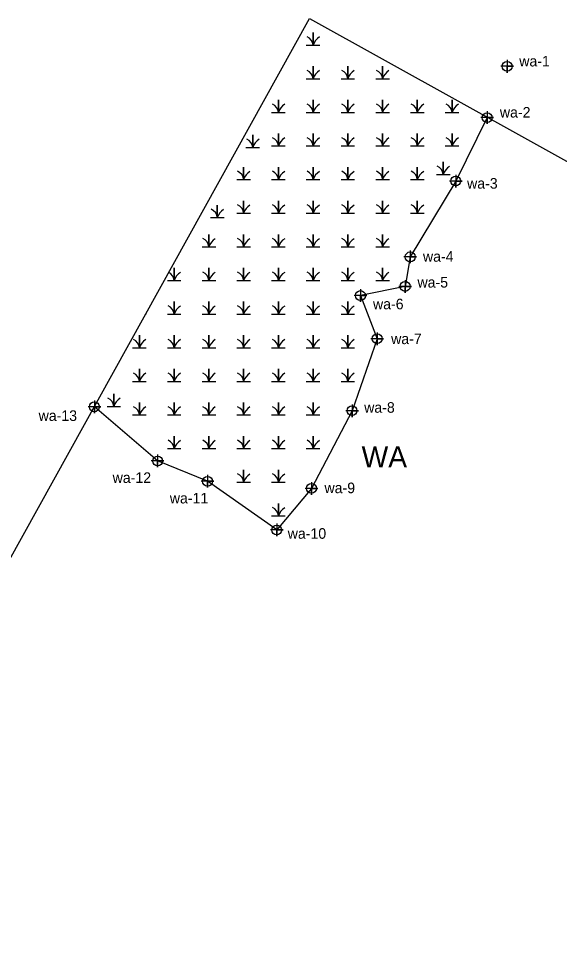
# Model space of a CAD drawing. Extents: x 2174810 to 2196950, y 76168 to 88270.
# Drawn here: x 2177275 to 2177531.1, y 78724.8 to 79164 of the extents above; entities that cross this region are included whole.
import ezdxf

# ---------------------------------------------------------------- set-up
doc = ezdxf.new("R2010")
doc.units = 0
for name, color, linetype in [('Default', 7, 'Continuous'), ('Exist Environmental Wetland Boundary', 7, 'Continuous'), ('Exist Environmental Wetland Boundary Cogo Number', 7, 'Continuous'), ('Exist Environmental Wetland Boundary Cogo Point CELL', 7, 'Continuous'), ('Exist Environmental Wetland Boundary Text', 7, 'Continuous'), ('Exist Hydro Swamp or Marsh', 7, 'Continuous')]:
    doc.layers.add(name, color=color, linetype=linetype)

msp = doc.modelspace()

# ---------------------------------------------------------------- linework, layer by layer
at = {"layer": 'Default'}
msp.add_lwpolyline([(2175864.96, 77468.65), (2175974.98, 78067.37), (2175948.66, 78270.55), (2176147, 78296.25), (2176199.64, 77889.88), (2176204.55, 77860.59), (2176211.62, 77831.74), (2176220.8, 77803.5), (2176232.06, 77776.01), (2176245.32, 77749.44), (2176260.52, 77723.93), (2176492.8, 77599.18), (2176546.77, 77667.81), (2176598.73, 77737.98), (2176648.61, 77809.64), (2176696.4, 77882.71), (2176742.03, 77957.15), (2176785.48, 78032.88), (2177412.72, 79163.99), (2177762.53, 78970.01), (2177135.29, 77838.9), (2177091.17, 77761.72), (2177045.03, 77685.72), (2176996.93, 77610.95)], dxfattribs=at)
at = {"layer": 'Exist Environmental Wetland Boundary'}
msp.add_lwpolyline([(2177496.94, 79117.29), (2177496.87, 79117.09), (2177481.99, 79087.09), (2177460.42, 79051.18), (2177458.02, 79037.2), (2177436.88, 79032.86), (2177444.78, 79012.46), (2177432.88, 78978.36), (2177413.67, 78941.61), (2177397.22, 78921.92), (2177364.45, 78944.95), (2177340.81, 78954.58), (2177310.88, 78980.2)], dxfattribs=at)
at = {"layer": 'Exist Environmental Wetland Boundary Cogo Point CELL'}
for points in [[(2177506.32, 79144.38), (2177506.32, 79138.38), (2177506.32, 79141.38), (2177509.32, 79141.38), (2177503.32, 79141.38)], [(2177496.87, 79120.09), (2177496.87, 79114.09), (2177496.87, 79117.09), (2177499.87, 79117.09), (2177493.87, 79117.09)], [(2177481.99, 79090.09), (2177481.99, 79084.09), (2177481.99, 79087.09), (2177484.99, 79087.09), (2177478.99, 79087.09)], [(2177460.42, 79054.18), (2177460.42, 79048.18), (2177460.42, 79051.18), (2177463.42, 79051.18), (2177457.42, 79051.18)], [(2177458.02, 79040.2), (2177458.02, 79034.2), (2177458.02, 79037.2), (2177461.02, 79037.2), (2177455.02, 79037.2)], [(2177436.88, 79035.86), (2177436.88, 79029.86), (2177436.88, 79032.86), (2177439.88, 79032.86), (2177433.88, 79032.86)], [(2177444.78, 79015.46), (2177444.78, 79009.46), (2177444.78, 79012.46), (2177447.78, 79012.46), (2177441.78, 79012.46)], [(2177310.88, 78983.2), (2177310.88, 78977.2), (2177310.88, 78980.2), (2177313.88, 78980.2), (2177307.88, 78980.2)], [(2177432.88, 78981.36), (2177432.88, 78975.36), (2177432.88, 78978.36), (2177435.88, 78978.36), (2177429.88, 78978.36)], [(2177340.81, 78957.58), (2177340.81, 78951.58), (2177340.81, 78954.58), (2177343.81, 78954.58), (2177337.81, 78954.58)], [(2177364.45, 78947.95), (2177364.45, 78941.95), (2177364.45, 78944.95), (2177367.45, 78944.95), (2177361.45, 78944.95)], [(2177413.67, 78944.61), (2177413.67, 78938.61), (2177413.67, 78941.61), (2177416.67, 78941.61), (2177410.67, 78941.61)], [(2177397.22, 78924.92), (2177397.22, 78918.92), (2177397.22, 78921.92), (2177400.22, 78921.92), (2177394.22, 78921.92)]]:
    msp.add_lwpolyline(points, dxfattribs=at)
for centre in [(2177506.32, 79141.38), (2177496.87, 79117.09), (2177481.99, 79087.09), (2177460.42, 79051.18), (2177458.02, 79037.2), (2177436.88, 79032.86), (2177444.78, 79012.46), (2177310.88, 78980.2), (2177432.88, 78978.36), (2177340.81, 78954.58), (2177364.45, 78944.95), (2177413.67, 78941.61), (2177397.22, 78921.92)]:
    msp.add_circle(centre, 2.34, dxfattribs=at)
at = {"layer": 'Exist Hydro Swamp or Marsh'}
msp.add_line((2177335.2, 79024.09), (2177335.42, 79024.09), dxfattribs=at)
for points in [[(2177411.22, 79151.44), (2177414.45, 79151.44), (2177414.45, 79157.35), (2177414.45, 79151.44), (2177417.67, 79151.44)], [(2177411.22, 79135.52), (2177414.45, 79135.52), (2177414.45, 79141.44), (2177414.45, 79135.52), (2177417.67, 79135.52)], [(2177427.67, 79135.52), (2177430.9, 79135.52), (2177430.9, 79141.44), (2177430.9, 79135.52), (2177434.12, 79135.52)], [(2177444.12, 79135.52), (2177447.35, 79135.52), (2177447.35, 79141.44), (2177447.35, 79135.52), (2177450.57, 79135.52)], [(2177394.77, 79119.6), (2177398, 79119.6), (2177398, 79125.52), (2177398, 79119.6), (2177401.22, 79119.6)], [(2177411.22, 79119.6), (2177414.45, 79119.6), (2177414.45, 79125.52), (2177414.45, 79119.6), (2177417.67, 79119.6)], [(2177427.67, 79119.6), (2177430.9, 79119.6), (2177430.9, 79125.52), (2177430.9, 79119.6), (2177434.12, 79119.6)], [(2177444.12, 79119.6), (2177447.35, 79119.6), (2177447.35, 79125.52), (2177447.35, 79119.6), (2177450.57, 79119.6)], [(2177460.57, 79119.6), (2177463.8, 79119.6), (2177463.8, 79125.52), (2177463.8, 79119.6), (2177467.03, 79119.6)], [(2177477.03, 79119.6), (2177480.25, 79119.6), (2177480.25, 79125.52), (2177480.25, 79119.6), (2177483.48, 79119.6)], [(2177382.65, 79103.02), (2177385.87, 79103.02), (2177385.87, 79108.94), (2177385.87, 79103.02), (2177389.1, 79103.02)], [(2177394.77, 79103.68), (2177398, 79103.68), (2177398, 79109.6), (2177398, 79103.68), (2177401.22, 79103.68)], [(2177411.22, 79103.68), (2177414.45, 79103.68), (2177414.45, 79109.6), (2177414.45, 79103.68), (2177417.67, 79103.68)], [(2177427.67, 79103.68), (2177430.9, 79103.68), (2177430.9, 79109.6), (2177430.9, 79103.68), (2177434.12, 79103.68)], [(2177444.12, 79103.68), (2177447.35, 79103.68), (2177447.35, 79109.6), (2177447.35, 79103.68), (2177450.57, 79103.68)], [(2177460.57, 79103.68), (2177463.8, 79103.68), (2177463.8, 79109.6), (2177463.8, 79103.68), (2177467.03, 79103.68)], [(2177477.03, 79103.68), (2177480.25, 79103.68), (2177480.25, 79109.6), (2177480.25, 79103.68), (2177483.48, 79103.68)], [(2177378.32, 79087.76), (2177381.54, 79087.76), (2177381.54, 79093.68), (2177381.54, 79087.76), (2177384.77, 79087.76)], [(2177394.77, 79087.76), (2177398, 79087.76), (2177398, 79093.68), (2177398, 79087.76), (2177401.22, 79087.76)], [(2177411.22, 79087.76), (2177414.45, 79087.76), (2177414.45, 79093.68), (2177414.45, 79087.76), (2177417.67, 79087.76)], [(2177427.67, 79087.76), (2177430.9, 79087.76), (2177430.9, 79093.68), (2177430.9, 79087.76), (2177434.12, 79087.76)], [(2177444.12, 79087.76), (2177447.35, 79087.76), (2177447.35, 79093.68), (2177447.35, 79087.76), (2177450.57, 79087.76)], [(2177460.57, 79087.76), (2177463.8, 79087.76), (2177463.8, 79093.68), (2177463.8, 79087.76), (2177467.03, 79087.76)], [(2177472.84, 79090.2), (2177476.07, 79090.2), (2177476.07, 79096.12), (2177476.07, 79090.2), (2177479.3, 79090.2)], [(2177365.85, 79069.77), (2177369.08, 79069.77), (2177369.08, 79075.69), (2177369.08, 79069.77), (2177372.3, 79069.77)], [(2177378.32, 79071.85), (2177381.54, 79071.85), (2177381.54, 79077.76), (2177381.54, 79071.85), (2177384.77, 79071.85)], [(2177394.77, 79071.85), (2177398, 79071.85), (2177398, 79077.76), (2177398, 79071.85), (2177401.22, 79071.85)], [(2177411.22, 79071.85), (2177414.45, 79071.85), (2177414.45, 79077.76), (2177414.45, 79071.85), (2177417.67, 79071.85)], [(2177427.67, 79071.85), (2177430.9, 79071.85), (2177430.9, 79077.76), (2177430.9, 79071.85), (2177434.12, 79071.85)], [(2177444.12, 79071.85), (2177447.35, 79071.85), (2177447.35, 79077.76), (2177447.35, 79071.85), (2177450.57, 79071.85)], [(2177460.57, 79071.85), (2177463.8, 79071.85), (2177463.8, 79077.76), (2177463.8, 79071.85), (2177467.03, 79071.85)], [(2177361.87, 79055.93), (2177365.09, 79055.93), (2177365.09, 79061.85), (2177365.09, 79055.93), (2177368.32, 79055.93)], [(2177378.32, 79055.93), (2177381.54, 79055.93), (2177381.54, 79061.85), (2177381.54, 79055.93), (2177384.77, 79055.93)], [(2177394.77, 79055.93), (2177398, 79055.93), (2177398, 79061.85), (2177398, 79055.93), (2177401.22, 79055.93)], [(2177411.22, 79055.93), (2177414.45, 79055.93), (2177414.45, 79061.85), (2177414.45, 79055.93), (2177417.67, 79055.93)], [(2177427.67, 79055.93), (2177430.9, 79055.93), (2177430.9, 79061.85), (2177430.9, 79055.93), (2177434.12, 79055.93)], [(2177444.12, 79055.93), (2177447.35, 79055.93), (2177447.35, 79061.85), (2177447.35, 79055.93), (2177450.57, 79055.93)], [(2177345.42, 79040.01), (2177348.64, 79040.01), (2177348.64, 79045.93), (2177348.64, 79040.01), (2177351.87, 79040.01)], [(2177361.87, 79040.01), (2177365.09, 79040.01), (2177365.09, 79045.93), (2177365.09, 79040.01), (2177368.32, 79040.01)], [(2177378.32, 79040.01), (2177381.54, 79040.01), (2177381.54, 79045.93), (2177381.54, 79040.01), (2177384.77, 79040.01)], [(2177394.77, 79040.01), (2177398, 79040.01), (2177398, 79045.93), (2177398, 79040.01), (2177401.22, 79040.01)], [(2177411.22, 79040.01), (2177414.45, 79040.01), (2177414.45, 79045.93), (2177414.45, 79040.01), (2177417.67, 79040.01)], [(2177427.67, 79040.01), (2177430.9, 79040.01), (2177430.9, 79045.93), (2177430.9, 79040.01), (2177434.12, 79040.01)], [(2177444.12, 79040.01), (2177447.35, 79040.01), (2177447.35, 79045.93), (2177447.35, 79040.01), (2177450.57, 79040.01)], [(2177345.42, 79024.09), (2177348.64, 79024.09), (2177348.64, 79030.01), (2177348.64, 79024.09), (2177351.87, 79024.09)], [(2177361.87, 79024.09), (2177365.09, 79024.09), (2177365.09, 79030.01), (2177365.09, 79024.09), (2177368.32, 79024.09)], [(2177378.32, 79024.09), (2177381.54, 79024.09), (2177381.54, 79030.01), (2177381.54, 79024.09), (2177384.77, 79024.09)], [(2177394.77, 79024.09), (2177398, 79024.09), (2177398, 79030.01), (2177398, 79024.09), (2177401.22, 79024.09)], [(2177411.22, 79024.09), (2177414.45, 79024.09), (2177414.45, 79030.01), (2177414.45, 79024.09), (2177417.67, 79024.09)], [(2177427.67, 79024.09), (2177430.9, 79024.09), (2177430.9, 79030.01), (2177430.9, 79024.09), (2177434.12, 79024.09)], [(2177328.96, 79008.18), (2177332.19, 79008.18), (2177332.19, 79014.09), (2177332.19, 79008.18), (2177335.42, 79008.18)], [(2177345.42, 79008.18), (2177348.64, 79008.18), (2177348.64, 79014.09), (2177348.64, 79008.18), (2177351.87, 79008.18)], [(2177361.87, 79008.18), (2177365.09, 79008.18), (2177365.09, 79014.09), (2177365.09, 79008.18), (2177368.32, 79008.18)], [(2177378.32, 79008.18), (2177381.54, 79008.18), (2177381.54, 79014.09), (2177381.54, 79008.18), (2177384.77, 79008.18)], [(2177394.77, 79008.18), (2177398, 79008.18), (2177398, 79014.09), (2177398, 79008.18), (2177401.22, 79008.18)], [(2177411.22, 79008.18), (2177414.45, 79008.18), (2177414.45, 79014.09), (2177414.45, 79008.18), (2177417.67, 79008.18)], [(2177427.67, 79008.18), (2177430.9, 79008.18), (2177430.9, 79014.09), (2177430.9, 79008.18), (2177434.12, 79008.18)], [(2177328.96, 78992.26), (2177332.19, 78992.26), (2177332.19, 78998.18), (2177332.19, 78992.26), (2177335.42, 78992.26)], [(2177345.42, 78992.26), (2177348.64, 78992.26), (2177348.64, 78998.18), (2177348.64, 78992.26), (2177351.87, 78992.26)], [(2177361.87, 78992.26), (2177365.09, 78992.26), (2177365.09, 78998.18), (2177365.09, 78992.26), (2177368.32, 78992.26)], [(2177378.32, 78992.26), (2177381.54, 78992.26), (2177381.54, 78998.18), (2177381.54, 78992.26), (2177384.77, 78992.26)], [(2177394.77, 78992.26), (2177398, 78992.26), (2177398, 78998.18), (2177398, 78992.26), (2177401.22, 78992.26)], [(2177411.22, 78992.26), (2177414.45, 78992.26), (2177414.45, 78998.18), (2177414.45, 78992.26), (2177417.67, 78992.26)], [(2177427.67, 78992.26), (2177430.9, 78992.26), (2177430.9, 78998.18), (2177430.9, 78992.26), (2177434.12, 78992.26)], [(2177316.86, 78980.41), (2177320.08, 78980.41), (2177320.08, 78986.32), (2177320.08, 78980.41), (2177323.31, 78980.41)], [(2177328.96, 78976.34), (2177332.19, 78976.34), (2177332.19, 78982.26), (2177332.19, 78976.34), (2177335.42, 78976.34)], [(2177345.42, 78976.34), (2177348.64, 78976.34), (2177348.64, 78982.26), (2177348.64, 78976.34), (2177351.87, 78976.34)], [(2177361.87, 78976.34), (2177365.09, 78976.34), (2177365.09, 78982.26), (2177365.09, 78976.34), (2177368.32, 78976.34)], [(2177378.32, 78976.34), (2177381.54, 78976.34), (2177381.54, 78982.26), (2177381.54, 78976.34), (2177384.77, 78976.34)], [(2177394.77, 78976.34), (2177398, 78976.34), (2177398, 78982.26), (2177398, 78976.34), (2177401.22, 78976.34)], [(2177411.22, 78976.34), (2177414.45, 78976.34), (2177414.45, 78982.26), (2177414.45, 78976.34), (2177417.67, 78976.34)], [(2177345.42, 78960.42), (2177348.64, 78960.42), (2177348.64, 78966.34), (2177348.64, 78960.42), (2177351.87, 78960.42)], [(2177361.87, 78960.42), (2177365.09, 78960.42), (2177365.09, 78966.34), (2177365.09, 78960.42), (2177368.32, 78960.42)], [(2177378.32, 78960.42), (2177381.54, 78960.42), (2177381.54, 78966.34), (2177381.54, 78960.42), (2177384.77, 78960.42)], [(2177394.77, 78960.42), (2177398, 78960.42), (2177398, 78966.34), (2177398, 78960.42), (2177401.22, 78960.42)], [(2177411.22, 78960.42), (2177414.45, 78960.42), (2177414.45, 78966.34), (2177414.45, 78960.42), (2177417.67, 78960.42)], [(2177378.32, 78944.51), (2177381.54, 78944.51), (2177381.54, 78950.42), (2177381.54, 78944.51), (2177384.77, 78944.51)], [(2177394.77, 78944.51), (2177398, 78944.51), (2177398, 78950.42), (2177398, 78944.51), (2177401.22, 78944.51)], [(2177394.77, 78928.59), (2177398, 78928.59), (2177398, 78934.51), (2177398, 78928.59), (2177401.22, 78928.59)]]:
    msp.add_lwpolyline(points, dxfattribs=at)
for centre, radius, start, end in [((2177409.85, 79151.1), 4.61, 4.1403, 67.535), ((2177421.29, 79149.16), 7.21, 122.1274, 161.6222), ((2177409.85, 79135.18), 4.61, 4.1403, 67.535), ((2177421.29, 79133.24), 7.21, 122.1274, 161.6222), ((2177426.3, 79135.18), 4.61, 4.1403, 67.535), ((2177437.74, 79133.24), 7.21, 122.1274, 161.6222), ((2177442.75, 79135.18), 4.61, 4.1403, 67.535), ((2177454.19, 79133.24), 7.21, 122.1274, 161.6222), ((2177393.4, 79119.27), 4.61, 4.1403, 67.535), ((2177404.84, 79117.33), 7.21, 122.1274, 161.6222), ((2177409.85, 79119.27), 4.61, 4.1403, 67.535), ((2177421.29, 79117.33), 7.21, 122.1274, 161.6222), ((2177426.3, 79119.27), 4.61, 4.1403, 67.535), ((2177437.74, 79117.33), 7.21, 122.1274, 161.6222), ((2177442.75, 79119.27), 4.61, 4.1403, 67.535), ((2177454.19, 79117.33), 7.21, 122.1274, 161.6222), ((2177459.2, 79119.27), 4.61, 4.1403, 67.535), ((2177470.64, 79117.33), 7.21, 122.1274, 161.6222), ((2177475.65, 79119.27), 4.61, 4.1403, 67.535), ((2177487.09, 79117.33), 7.21, 122.1274, 161.6222), ((2177381.27, 79102.69), 4.61, 4.1403, 67.535), ((2177392.71, 79100.75), 7.21, 122.1274, 161.6222), ((2177393.4, 79103.35), 4.61, 4.1403, 67.535), ((2177404.84, 79101.41), 7.21, 122.1274, 161.6222), ((2177409.85, 79103.35), 4.61, 4.1403, 67.535), ((2177421.29, 79101.41), 7.21, 122.1274, 161.6222), ((2177426.3, 79103.35), 4.61, 4.1403, 67.535), ((2177437.74, 79101.41), 7.21, 122.1274, 161.6222), ((2177442.75, 79103.35), 4.61, 4.1403, 67.535), ((2177454.19, 79101.41), 7.21, 122.1274, 161.6222), ((2177459.2, 79103.35), 4.61, 4.1403, 67.535), ((2177470.64, 79101.41), 7.21, 122.1274, 161.6222), ((2177475.65, 79103.35), 4.61, 4.1403, 67.535), ((2177487.09, 79101.41), 7.21, 122.1274, 161.6222), ((2177471.47, 79089.87), 4.61, 4.1403, 67.535), ((2177482.91, 79087.93), 7.21, 122.1274, 161.6222), ((2177376.94, 79087.43), 4.61, 4.1403, 67.535), ((2177388.38, 79085.49), 7.21, 122.1274, 161.6222), ((2177393.4, 79087.43), 4.61, 4.1403, 67.535), ((2177404.84, 79085.49), 7.21, 122.1274, 161.6222), ((2177409.85, 79087.43), 4.61, 4.1403, 67.535), ((2177421.29, 79085.49), 7.21, 122.1274, 161.6222), ((2177426.3, 79087.43), 4.61, 4.1403, 67.535), ((2177437.74, 79085.49), 7.21, 122.1274, 161.6222), ((2177442.75, 79087.43), 4.61, 4.1403, 67.535), ((2177454.19, 79085.49), 7.21, 122.1274, 161.6222), ((2177459.2, 79087.43), 4.61, 4.1403, 67.535), ((2177470.64, 79085.49), 7.21, 122.1274, 161.6222), ((2177376.94, 79071.51), 4.61, 4.1403, 67.535), ((2177388.38, 79069.57), 7.21, 122.1274, 161.6222), ((2177393.4, 79071.51), 4.61, 4.1403, 67.535), ((2177404.84, 79069.57), 7.21, 122.1274, 161.6222), ((2177409.85, 79071.51), 4.61, 4.1403, 67.535), ((2177421.29, 79069.57), 7.21, 122.1274, 161.6222), ((2177426.3, 79071.51), 4.61, 4.1403, 67.535), ((2177437.74, 79069.57), 7.21, 122.1274, 161.6222), ((2177442.75, 79071.51), 4.61, 4.1403, 67.535), ((2177454.19, 79069.57), 7.21, 122.1274, 161.6222), ((2177459.2, 79071.51), 4.61, 4.1403, 67.535), ((2177470.64, 79069.57), 7.21, 122.1274, 161.6222), ((2177364.48, 79069.44), 4.61, 4.1403, 67.535), ((2177375.92, 79067.5), 7.21, 122.1274, 161.6222), ((2177360.49, 79055.6), 4.61, 4.1403, 67.535), ((2177371.93, 79053.66), 7.21, 122.1274, 161.6222), ((2177376.94, 79055.6), 4.61, 4.1403, 67.535), ((2177388.38, 79053.66), 7.21, 122.1274, 161.6222), ((2177393.4, 79055.6), 4.61, 4.1403, 67.535), ((2177404.84, 79053.66), 7.21, 122.1274, 161.6222), ((2177409.85, 79055.6), 4.61, 4.1403, 67.535), ((2177421.29, 79053.66), 7.21, 122.1274, 161.6222), ((2177426.3, 79055.6), 4.61, 4.1403, 67.535), ((2177437.74, 79053.66), 7.21, 122.1274, 161.6222), ((2177442.75, 79055.6), 4.61, 4.1403, 67.535), ((2177454.19, 79053.66), 7.21, 122.1274, 161.6222), ((2177344.04, 79039.68), 4.61, 4.1403, 63.2391), ((2177355.48, 79037.74), 7.21, 122.1274, 161.6222), ((2177360.49, 79039.68), 4.61, 4.1403, 67.535), ((2177371.93, 79037.74), 7.21, 122.1274, 161.6222), ((2177376.94, 79039.68), 4.61, 4.1403, 67.535), ((2177388.38, 79037.74), 7.21, 122.1274, 161.6222), ((2177393.4, 79039.68), 4.61, 4.1403, 67.535), ((2177404.84, 79037.74), 7.21, 122.1274, 161.6222), ((2177409.85, 79039.68), 4.61, 4.1403, 67.535), ((2177421.29, 79037.74), 7.21, 122.1274, 161.6222), ((2177426.3, 79039.68), 4.61, 4.1403, 67.535), ((2177437.74, 79037.74), 7.21, 122.1274, 161.6222), ((2177442.75, 79039.68), 4.61, 4.1403, 67.535), ((2177454.19, 79037.74), 7.21, 122.1274, 161.6222), ((2177344.04, 79023.76), 4.61, 4.1403, 67.535), ((2177355.48, 79021.82), 7.21, 122.1274, 161.6222), ((2177360.49, 79023.76), 4.61, 4.1403, 67.535), ((2177371.93, 79021.82), 7.21, 122.1274, 161.6222), ((2177376.94, 79023.76), 4.61, 4.1403, 67.535), ((2177388.38, 79021.82), 7.21, 122.1274, 161.6222), ((2177393.4, 79023.76), 4.61, 4.1403, 67.535), ((2177404.84, 79021.82), 7.21, 122.1274, 161.6222), ((2177409.85, 79023.76), 4.61, 4.1403, 67.535), ((2177421.29, 79021.82), 7.21, 122.1274, 161.6222), ((2177426.3, 79023.76), 4.61, 4.1403, 67.535), ((2177437.74, 79021.82), 7.21, 122.1274, 161.6222), ((2177327.59, 79007.84), 4.61, 4.1403, 67.535), ((2177339.03, 79005.9), 7.21, 122.1274, 161.6222), ((2177344.04, 79007.84), 4.61, 4.1403, 67.535), ((2177355.48, 79005.9), 7.21, 122.1274, 161.6222), ((2177360.49, 79007.84), 4.61, 4.1403, 67.535), ((2177371.93, 79005.9), 7.21, 122.1274, 161.6222), ((2177376.94, 79007.84), 4.61, 4.1403, 67.535), ((2177388.38, 79005.9), 7.21, 122.1274, 161.6222), ((2177393.4, 79007.84), 4.61, 4.1403, 67.535), ((2177404.84, 79005.9), 7.21, 122.1274, 161.6222), ((2177409.85, 79007.84), 4.61, 4.1403, 67.535), ((2177421.29, 79005.9), 7.21, 122.1274, 161.6222), ((2177426.3, 79007.84), 4.61, 4.1403, 67.535), ((2177437.74, 79005.9), 7.21, 122.1274, 161.6222), ((2177442.75, 79007.84), 4.61, 65.866, 67.535), ((2177327.59, 78991.93), 4.61, 4.1403, 67.535), ((2177339.03, 78989.99), 7.21, 122.1274, 161.6222), ((2177344.04, 78991.93), 4.61, 4.1403, 67.535), ((2177355.48, 78989.99), 7.21, 122.1274, 161.6222), ((2177360.49, 78991.93), 4.61, 4.1403, 67.535), ((2177371.93, 78989.99), 7.21, 122.1274, 161.6222), ((2177376.94, 78991.93), 4.61, 4.1403, 67.535), ((2177388.38, 78989.99), 7.21, 122.1274, 161.6222), ((2177393.4, 78991.93), 4.61, 4.1403, 67.535), ((2177404.84, 78989.99), 7.21, 122.1274, 161.6222), ((2177409.85, 78991.93), 4.61, 4.1403, 67.535), ((2177421.29, 78989.99), 7.21, 122.1274, 161.6222), ((2177426.3, 78991.93), 4.61, 4.1403, 67.535), ((2177437.74, 78989.99), 7.21, 122.1274, 161.6222), ((2177315.48, 78980.07), 4.61, 4.1403, 67.535), ((2177326.93, 78978.13), 7.21, 122.1274, 161.6222), ((2177327.59, 78976.01), 4.61, 4.1403, 67.535), ((2177339.03, 78974.07), 7.21, 122.1274, 161.6222), ((2177344.04, 78976.01), 4.61, 4.1403, 67.535), ((2177355.48, 78974.07), 7.21, 122.1274, 161.6222), ((2177360.49, 78976.01), 4.61, 4.1403, 67.535), ((2177371.93, 78974.07), 7.21, 122.1274, 161.6222), ((2177376.94, 78976.01), 4.61, 4.1403, 67.535), ((2177388.38, 78974.07), 7.21, 122.1274, 161.6222), ((2177393.4, 78976.01), 4.61, 4.1403, 67.535), ((2177404.84, 78974.07), 7.21, 122.1274, 161.6222), ((2177409.85, 78976.01), 4.61, 4.1403, 67.535), ((2177421.29, 78974.07), 7.21, 122.1274, 161.6222), ((2177344.04, 78960.09), 4.61, 4.1403, 67.535), ((2177355.48, 78958.15), 7.21, 122.1274, 161.6222), ((2177360.49, 78960.09), 4.61, 4.1403, 67.535), ((2177371.93, 78958.15), 7.21, 122.1274, 161.6222), ((2177376.94, 78960.09), 4.61, 4.1403, 67.535), ((2177388.38, 78958.15), 7.21, 122.1274, 161.6222), ((2177393.4, 78960.09), 4.61, 4.1403, 67.535), ((2177404.84, 78958.15), 7.21, 122.1274, 161.6222), ((2177409.85, 78960.09), 4.61, 4.1403, 67.535), ((2177421.29, 78958.15), 7.21, 122.1274, 161.6222), ((2177376.94, 78944.17), 4.61, 4.1403, 67.535), ((2177388.38, 78942.23), 7.21, 122.1274, 161.6222), ((2177393.4, 78944.17), 4.61, 4.1403, 67.535), ((2177404.84, 78942.23), 7.21, 122.1274, 161.6222), ((2177393.4, 78928.25), 4.61, 4.1403, 67.535), ((2177404.84, 78926.31), 7.21, 122.1274, 161.6222)]:
    msp.add_arc(centre, radius, start, end, dxfattribs=at)

# ---------------------------------------------------------------- texts
at = {"layer": 'Exist Environmental Wetland Boundary Cogo Number'}
for s, p in [('wa-1', (2177512.06, 79141.34)), ('wa-2', (2177502.89, 79117.13)), ('wa-3', (2177487.35, 79083.47)), ('wa-4', (2177466.46, 79048.89)), ('wa-5', (2177463.87, 79036.65)), ('wa-6', (2177442.8, 79026.37)), ('wa-7', (2177451.38, 79009.89)), ('wa-8', (2177438.62, 78977.4)), ('wa-13', (2177284.46, 78973.53)), ('wa-12', (2177319.51, 78944.17)), ('wa-9', (2177419.83, 78939.33)), ('wa-11', (2177346.59, 78934.47)), ('wa-10', (2177402.42, 78917.75))]:
    msp.add_text(s, height=5, dxfattribs=at).set_placement(p)
at = {"layer": 'Exist Environmental Wetland Boundary Text'}
msp.add_text('WA', height=10, dxfattribs=at).set_placement((2177437.41, 78951.51))

doc.saveas('drawing.dxf')
